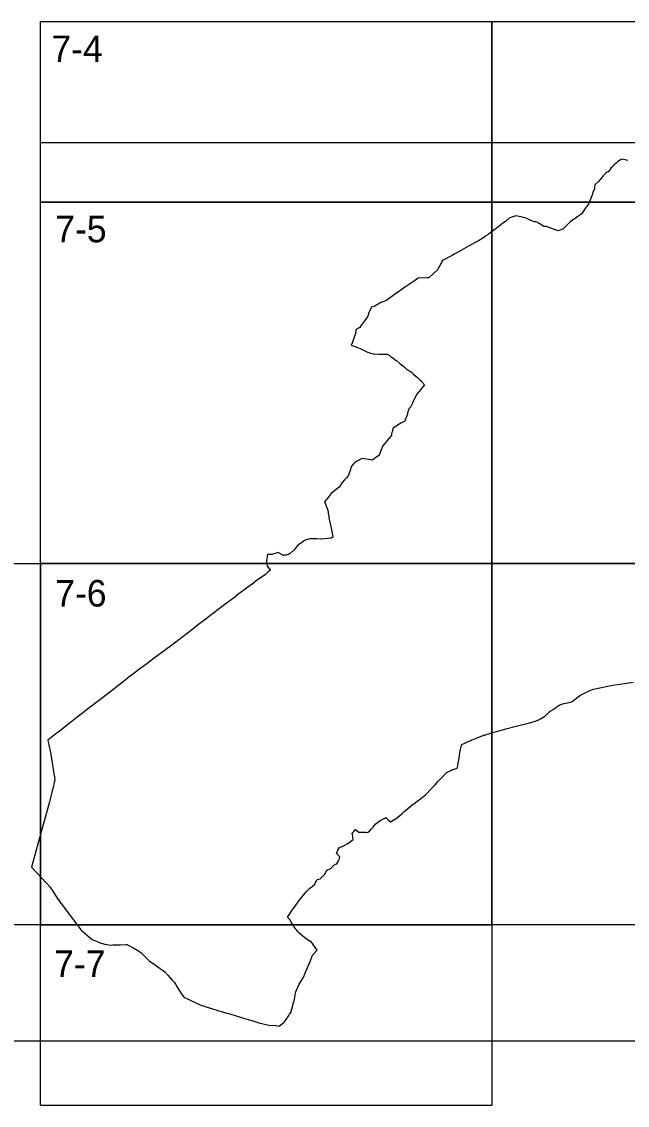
# Model space of a CAD drawing. Extents: x -449577 to -425530, y -1150048 to -1121091.
# Drawn here: x -438428.2 to -438218.5, y -1126653.4 to -1126278.4 of the extents above; entities that cross this region are included whole.
import ezdxf

# ---------------------------------------------------------------- set-up
doc = ezdxf.new("R2010")
doc.units = 0
for name, color, linetype in [('Vrstva 1', 7, 'Continuous'), ('Vrstva 10', 7, 'Continuous'), ('Vrstva 4', 7, 'Continuous')]:
    doc.layers.add(name, color=color, linetype=linetype)

msp = doc.modelspace()

# ---------------------------------------------------------------- linework, layer by layer
at = {"layer": 'Vrstva 1'}
for points in [[(-438218.3, -1126326.41), (-438218.76, -1126326.32), (-438220.35, -1126326), (-438220.65, -1126326.11), (-438221.21, -1126326.46), (-438221.76, -1126326.78), (-438222.25, -1126327.24), (-438222.78, -1126327.73), (-438223.18, -1126328.12), (-438223.19, -1126328.13), (-438223.52, -1126328.47), (-438223.65, -1126328.61), (-438224.16, -1126329.16), (-438224.61, -1126329.71), (-438224.77, -1126329.9), (-438225.13, -1126330.33), (-438225.87, -1126330.66), (-438225.89, -1126330.66), (-438226.09, -1126330.91), (-438226.95, -1126331.93), (-438227.33, -1126332.38), (-438228.46, -1126333.74), (-438228.47, -1126333.75), (-438229.71, -1126334.92), (-438229.83, -1126335.76), (-438229.88, -1126336.13), (-438229.92, -1126336.23), (-438230.4, -1126337.58), (-438230.84, -1126338.82), (-438230.87, -1126338.9), (-438231.17, -1126339.59), (-438232.1, -1126341.77), (-438232.12, -1126341.78), (-438232.69, -1126342.46), (-438232.99, -1126342.81), (-438232.99, -1126342.82), (-438233.33, -1126343.36), (-438234.2, -1126344.75), (-438234.29, -1126344.89), (-438234.46, -1126345.02), (-438234.99, -1126345.41), (-438235.6, -1126345.86), (-438235.6, -1126345.86), (-438236.57, -1126346.49), (-438236.7, -1126346.58), (-438236.88, -1126346.7), (-438238.18, -1126347.56), (-438238.19, -1126347.57), (-438238.45, -1126347.83), (-438238.57, -1126347.95), (-438238.79, -1126348.18), (-438239.07, -1126348.46), (-438239.64, -1126349.03), (-438240.8, -1126350.19), (-438241, -1126350.27), (-438242.5, -1126350.84), (-438245.31, -1126349.72), (-438245.31, -1126349.73), (-438245.32, -1126349.75), (-438246.23, -1126349.37), (-438246.54, -1126349.24), (-438246.56, -1126349.24), (-438246.95, -1126349.24), (-438247.43, -1126349.24), (-438248.99, -1126348.25), (-438249.25, -1126348.12), (-438249.54, -1126347.96), (-438249.6, -1126347.93), (-438249.64, -1126347.91), (-438250.18, -1126347.68), (-438250.23, -1126347.68), (-438250.24, -1126347.68), (-438250.39, -1126347.67), (-438250.51, -1126347.66), (-438250.82, -1126347.64), (-438250.84, -1126347.64), (-438250.84, -1126347.64), (-438250.95, -1126347.6), (-438251.19, -1126347.5), (-438251.79, -1126347.25), (-438251.95, -1126347.18), (-438253.47, -1126346.45), (-438254.09, -1126346.27), (-438254.76, -1126346.07), (-438257.08, -1126345.64), (-438257.09, -1126345.64), (-438257.49, -1126345.75), (-438259.23, -1126346.33), (-438259.36, -1126346.44), (-438260.57, -1126347.4), (-438260.57, -1126347.4), (-438261.72, -1126348.27), (-438262.29, -1126348.7), (-438262.87, -1126349.14), (-438263.03, -1126349.26), (-438265.16, -1126350.9), (-438266.23, -1126351.72), (-438266.7, -1126352.06), (-438267.46, -1126352.57), (-438267.71, -1126352.73), (-438268.3, -1126353.12), (-438268.34, -1126353.15), (-438268.55, -1126353.29), (-438269.46, -1126353.89), (-438269.47, -1126353.89), (-438269.94, -1126354.15), (-438270.09, -1126354.23), (-438270.27, -1126354.33), (-438270.73, -1126354.58), (-438270.91, -1126354.69), (-438271.07, -1126354.78), (-438271.17, -1126354.84), (-438271.41, -1126354.98), (-438273.07, -1126355.92), (-438273.24, -1126356.01), (-438273.47, -1126356.14), (-438275.94, -1126357.54), (-438276.06, -1126357.61), (-438278.17, -1126358.74), (-438279.19, -1126359.29), (-438282.53, -1126361.1), (-438282.7, -1126361.4), (-438282.76, -1126361.51), (-438283.54, -1126362.97), (-438284.22, -1126364.29), (-438284.36, -1126364.42), (-438284.45, -1126364.5), (-438285.59, -1126365.54), (-438287.1, -1126366.92), (-438287.27, -1126367.07), (-438287.27, -1126367.08), (-438287.74, -1126367.09), (-438290.93, -1126367.18), (-438290.94, -1126367.18), (-438291.37, -1126367.47), (-438292.2, -1126368.04), (-438294.67, -1126369.7), (-438294.71, -1126369.72), (-438294.95, -1126369.9), (-438295.22, -1126370.1), (-438298.2, -1126372.23), (-438298.27, -1126372.28), (-438301.27, -1126374.46), (-438301.74, -1126374.8), (-438301.9, -1126374.86), (-438303.84, -1126375.58), (-438303.85, -1126375.58), (-438304.24, -1126375.82), (-438306.12, -1126376.98), (-438307.04, -1126377.19), (-438307.29, -1126377.7), (-438308.05, -1126379.21), (-438308.06, -1126379.22), (-438308.13, -1126379.48), (-438308.33, -1126380.32), (-438309.16, -1126381.43), (-438310.53, -1126383.38), (-438311.09, -1126384.19), (-438311.12, -1126384.21), (-438312.28, -1126384.85), (-438312.38, -1126384.91), (-438312.45, -1126385.3), (-438312.6, -1126386.11), (-438312.65, -1126386.3), (-438313.94, -1126389.88), (-438314.11, -1126390.36), (-438314.08, -1126390.35), (-438314.06, -1126390.34), (-438313.38, -1126390.6), (-438311.57, -1126391.26), (-438310.95, -1126391.55), (-438308.66, -1126392.63), (-438308.64, -1126392.63), (-438307.48, -1126393.1), (-438307.01, -1126393.28), (-438306.98, -1126393.29), (-438306.55, -1126393.32), (-438306.41, -1126393.33), (-438306.19, -1126393.35), (-438304.59, -1126393.45), (-438303.55, -1126393.52), (-438302.5, -1126393.49), (-438301.66, -1126393.46), (-438301.65, -1126393.46), (-438301.37, -1126393.61), (-438301, -1126393.87), (-438300.45, -1126394.25), (-438300.06, -1126394.53), (-438298.5, -1126395.67), (-438298.33, -1126395.79), (-438297.22, -1126396.71), (-438296.83, -1126397.03), (-438296.65, -1126397.18), (-438295.9, -1126397.79), (-438295.63, -1126398.02), (-438295.03, -1126398.51), (-438294.81, -1126398.69), (-438294.17, -1126399.11), (-438293.42, -1126399.61), (-438293.39, -1126399.63), (-438292.63, -1126400.31), (-438291.75, -1126401.09), (-438291.31, -1126401.47), (-438290.3, -1126402.36), (-438290.04, -1126402.59), (-438289.99, -1126402.64), (-438289.89, -1126402.74), (-438289.88, -1126402.75), (-438289.79, -1126402.85), (-438289.76, -1126402.88), (-438288.71, -1126404.11), (-438288.72, -1126404.12), (-438289.16, -1126404.61), (-438289.22, -1126404.68), (-438289.79, -1126405.31), (-438290.61, -1126406.37), (-438290.78, -1126406.58), (-438291.34, -1126407.3), (-438291.64, -1126407.83), (-438291.66, -1126407.87), (-438291.67, -1126407.89), (-438291.8, -1126408.17), (-438292.6, -1126409.84), (-438292.91, -1126410.48), (-438293.53, -1126411.77), (-438293.64, -1126412.01), (-438293.65, -1126412.01), (-438293.69, -1126412.04), (-438293.98, -1126412.24), (-438294.06, -1126412.28), (-438294.11, -1126412.38), (-438294.2, -1126412.58), (-438294.29, -1126412.86), (-438294.46, -1126413.42), (-438294.47, -1126413.44), (-438294.59, -1126413.94), (-438294.61, -1126414.01), (-438294.6, -1126414.07), (-438294.59, -1126414.15), (-438294.59, -1126414.22), (-438294.6, -1126414.27), (-438295.48, -1126416.6), (-438295.5, -1126416.65), (-438295.52, -1126416.69), (-438295.53, -1126416.7), (-438296.23, -1126417), (-438296.48, -1126417.11), (-438296.95, -1126417.35), (-438299.56, -1126419.04), (-438299.56, -1126419.04), (-438299.93, -1126420.35), (-438300.01, -1126420.61), (-438300.12, -1126421.03), (-438300.18, -1126421.24), (-438300.18, -1126421.25), (-438300.17, -1126421.25), (-438300, -1126421.41), (-438300.01, -1126421.42), (-438300.37, -1126421.81), (-438301.17, -1126422.81), (-438301.18, -1126422.82), (-438301.39, -1126423.07), (-438301.39, -1126423.08), (-438301.51, -1126423.23), (-438302.67, -1126424.58), (-438303.21, -1126425.21), (-438303.97, -1126427.16), (-438304.35, -1126428.18), (-438304.48, -1126428.53), (-438306.01, -1126429.63), (-438306.63, -1126430.07), (-438306.81, -1126430.11), (-438306.83, -1126430.11), (-438307.46, -1126430.02), (-438310.3, -1126429.6), (-438310.79, -1126429.84), (-438312.12, -1126430.48), (-438312.66, -1126430.74), (-438312.69, -1126430.77), (-438313.12, -1126431.18), (-438313.29, -1126431.4), (-438313.95, -1126432.25), (-438313.95, -1126432.26), (-438314.62, -1126434.06), (-438315.19, -1126435.56), (-438315.19, -1126435.56), (-438315.33, -1126435.78), (-438315.66, -1126436.15), (-438316.38, -1126436.95), (-438317.08, -1126437.72), (-438317.09, -1126437.74), (-438317.22, -1126437.93), (-438318.29, -1126439.5), (-438318.76, -1126439.88), (-438320.33, -1126441.14), (-438321, -1126441.68), (-438321.1, -1126441.76), (-438321.13, -1126441.8), (-438322.25, -1126443.23), (-438323.39, -1126444.54), (-438323.24, -1126444.71), (-438323.23, -1126444.74), (-438323.23, -1126444.75), (-438322.22, -1126447.51), (-438321.94, -1126449.17), (-438321.62, -1126451.12), (-438321.21, -1126453.08), (-438320.48, -1126456.58), (-438320.44, -1126456.78), (-438321.09, -1126457.12), (-438321.21, -1126457.19), (-438324.38, -1126457.45), (-438324.54, -1126457.45), (-438326.03, -1126457.42), (-438328.42, -1126457.4), (-438329.7, -1126457.67), (-438330.3, -1126457.94), (-438331.28, -1126458.74), (-438332.58, -1126459.61), (-438332.67, -1126459.72), (-438333.83, -1126461.14), (-438335.28, -1126462.48), (-438335.97, -1126462.8), (-438336.57, -1126463.08), (-438337.74, -1126463.01), (-438339.35, -1126462.16), (-438341.59, -1126462.83), (-438343.07, -1126462.8), (-438343.45, -1126464.91), (-438343.46, -1126464.93), (-438343.47, -1126465.02), (-438343.18, -1126466.83), (-438342.21, -1126468.15), (-438342.2, -1126468.17), (-438342.94, -1126468.92), (-438343.55, -1126469.48), (-438343.8, -1126469.71), (-438344.6, -1126470.34), (-438346.53, -1126471.57), (-438346.59, -1126471.61), (-438348.56, -1126473.14), (-438348.62, -1126473.18), (-438349.11, -1126473.56), (-438353.77, -1126477.02), (-438353.8, -1126477.05), (-438358.75, -1126480.81), (-438363.01, -1126484.06), (-438363.89, -1126484.72), (-438366.46, -1126486.66), (-438370.46, -1126489.79), (-438372.9, -1126491.66), (-438376.21, -1126494.19), (-438376.26, -1126494.23), (-438381.05, -1126497.74), (-438381.28, -1126497.92), (-438384.89, -1126500.6), (-438387.28, -1126502.42), (-438389.25, -1126503.9), (-438391.57, -1126505.65), (-438391.8, -1126505.82), (-438392.93, -1126506.71), (-438397.75, -1126510.51), (-438401.64, -1126513.46), (-438405.86, -1126516.71), (-438407.15, -1126517.71), (-438409.54, -1126519.59), (-438410.72, -1126520.51), (-438414.66, -1126523.56), (-438415.59, -1126524.27), (-438416.83, -1126525.23), (-438419.15, -1126527.03), (-438419.15, -1126527.03), (-438419.11, -1126527.21), (-438418.82, -1126528.59), (-438418.79, -1126528.75), (-438418.26, -1126531.29), (-438418.1, -1126532.02), (-438418.1, -1126532.06), (-438417.17, -1126537.94), (-438417.16, -1126537.97), (-438416.86, -1126539.7), (-438416.86, -1126539.72), (-438416.8, -1126540.09), (-438416.74, -1126540.51), (-438416.77, -1126540.88), (-438416.92, -1126541.61), (-438417.3, -1126543.4), (-438417.59, -1126544.58), (-438417.61, -1126544.63), (-438418.72, -1126548.8), (-438420.82, -1126556.68), (-438422.81, -1126563.9), (-438424.74, -1126571), (-438424.75, -1126571.04), (-438419.47, -1126576.64), (-438418.42, -1126577.77), (-438417.66, -1126578.99), (-438415.64, -1126582.05), (-438415.59, -1126582.12), (-438414.58, -1126583.53), (-438414.42, -1126583.74), (-438412.54, -1126586.22), (-438411.97, -1126586.96), (-438411.94, -1126587), (-438411.42, -1126587.72), (-438410.04, -1126589.62), (-438409.71, -1126590.07), (-438407.56, -1126592.79), (-438406.16, -1126594.01), (-438403.76, -1126595.99), (-438402.02, -1126596.74), (-438400.83, -1126597.26), (-438400.7, -1126597.31), (-438399.37, -1126597.59), (-438399.23, -1126597.62), (-438397.61, -1126597.95), (-438397.58, -1126597.95), (-438396.62, -1126597.93), (-438396.24, -1126597.93), (-438395.72, -1126597.92), (-438395.04, -1126597.91), (-438394.13, -1126597.87), (-438392.18, -1126597.71), (-438391.73, -1126597.78), (-438391.07, -1126598.13), (-438389.35, -1126599.08), (-438387.39, -1126600.18), (-438386.87, -1126600.66), (-438386.15, -1126601.34), (-438385.35, -1126602.09), (-438384.03, -1126603.39), (-438383.89, -1126603.49), (-438382.7, -1126604.34), (-438380.29, -1126606.05), (-438378.65, -1126607.23), (-438377.6, -1126608.41), (-438375.96, -1126610.23), (-438375.32, -1126610.94), (-438374.96, -1126611.53), (-438374.5, -1126612.27), (-438373.56, -1126613.74), (-438372.93, -1126614.66), (-438371.89, -1126616.1), (-438370.82, -1126616.61), (-438369.44, -1126617.26), (-438368.13, -1126617.87), (-438366.16, -1126618.76), (-438365.03, -1126619.11), (-438363.31, -1126619.68), (-438363.16, -1126619.73), (-438362.07, -1126620.05), (-438360.65, -1126620.47), (-438360.64, -1126620.47), (-438360.43, -1126620.53), (-438360.37, -1126620.55), (-438359.51, -1126620.81), (-438357.12, -1126621.5), (-438357, -1126621.54), (-438356.52, -1126621.68), (-438353.59, -1126622.55), (-438350.9, -1126623.38), (-438350.56, -1126623.48), (-438349.8, -1126623.71), (-438347.79, -1126624.33), (-438346.06, -1126624.88), (-438342.6, -1126625.62)], [(-438342.6, -1126625.62), (-438340.21, -1126625.81), (-438339.01, -1126626.04), (-438338.9, -1126625.95), (-438337.32, -1126624.68), (-438336.29, -1126623.2), (-438336.18, -1126623.05), (-438335.66, -1126622.29), (-438335.55, -1126622.12), (-438335.41, -1126621.89), (-438335.03, -1126621.26), (-438334.76, -1126620.43), (-438334.74, -1126620.36), (-438334.72, -1126620.31), (-438334.69, -1126620.2), (-438334.66, -1126620.11), (-438334.66, -1126620.1), (-438334.03, -1126617.9), (-438333.89, -1126617.38), (-438333.44, -1126614.63), (-438333.44, -1126614.63), (-438333.25, -1126614.19), (-438332.99, -1126613.57), (-438332.2, -1126611.74), (-438330.63, -1126609.09), (-438328.88, -1126604.96), (-438328.56, -1126604.32), (-438328.52, -1126604.19), (-438328.13, -1126603.09), (-438327.54, -1126601.42), (-438325.86, -1126599.71), (-438326.79, -1126598.47), (-438326.85, -1126598.38), (-438326.9, -1126598.32), (-438326.93, -1126598.28), (-438327, -1126598.18), (-438327.05, -1126598.1), (-438327.13, -1126597.98), (-438327.49, -1126597.46), (-438327.86, -1126597), (-438328.43, -1126596.63), (-438328.53, -1126596.57), (-438330.18, -1126595.5), (-438332.37, -1126593.56), (-438332.5, -1126593.39), (-438332.53, -1126593.35), (-438332.61, -1126593.25), (-438332.95, -1126592.83), (-438333.28, -1126592.42), (-438333.54, -1126592.1), (-438334.02, -1126591.51), (-438334.1, -1126591.41), (-438334.6, -1126590.45), (-438334.89, -1126589.89), (-438335.12, -1126589.46), (-438335.17, -1126589.37), (-438335.21, -1126589.32), (-438335.47, -1126589.03), (-438335.67, -1126588.8), (-438335.93, -1126588.51), (-438336.15, -1126588.26), (-438334.29, -1126585.52), (-438334.2, -1126585.4), (-438333.88, -1126584.95), (-438333.56, -1126584.51), (-438332.23, -1126582.68), (-438329.55, -1126579.42), (-438329.2, -1126579.1), (-438328.49, -1126578.4), (-438328.38, -1126578.31), (-438328.19, -1126578.17), (-438327.59, -1126577.69), (-438326.73, -1126576.85), (-438326.32, -1126576.09), (-438325.85, -1126575.22), (-438324.8, -1126574.98), (-438323.4, -1126573.55), (-438322.86, -1126572.7), (-438322.85, -1126572.69), (-438322.85, -1126572.67), (-438322.64, -1126572.34), (-438322.59, -1126572.26), (-438322.35, -1126571.87), (-438321.19, -1126571.43), (-438320.17, -1126570.25), (-438319.64, -1126570.05), (-438319.52, -1126570), (-438319.1, -1126569.84), (-438318.88, -1126569.45), (-438318.83, -1126569.36), (-438318.66, -1126569.06), (-438318.25, -1126568.32), (-438318.05, -1126567.41), (-438318.05, -1126567.39), (-438318.04, -1126567.38), (-438319.09, -1126566.39), (-438319.11, -1126566.38), (-438319.12, -1126566.36), (-438319.17, -1126566.32), (-438318.52, -1126564.52), (-438318.45, -1126564.32), (-438318.29, -1126564.26), (-438317.56, -1126563.97), (-438316.87, -1126563.7), (-438316.75, -1126563.65), (-438315.54, -1126562.94), (-438315.42, -1126562.86), (-438315.42, -1126562.86), (-438315.41, -1126562.85), (-438315.29, -1126562.78), (-438313.43, -1126561.38), (-438313.43, -1126561.34), (-438313.46, -1126561.18), (-438313.53, -1126560.7), (-438313.59, -1126560.35), (-438313.69, -1126559.73), (-438313.71, -1126559.62), (-438313.73, -1126559.49), (-438313.75, -1126559.32), (-438313.78, -1126559.18), (-438313.24, -1126558.62), (-438312.68, -1126558.05), (-438312.64, -1126558), (-438312.5, -1126558.1), (-438311.5, -1126558.89), (-438310.82, -1126558.9), (-438310.76, -1126558.9), (-438310.51, -1126558.91), (-438310.35, -1126558.91), (-438309.04, -1126558.93), (-438308.41, -1126558.95), (-438308.14, -1126558.79), (-438308.11, -1126558.77), (-438307.99, -1126558.7), (-438307.85, -1126558.61), (-438307.81, -1126558.58), (-438307.27, -1126557.98), (-438307.16, -1126557.86), (-438307.07, -1126557.76), (-438306.9, -1126557.58), (-438306.82, -1126557.49), (-438306.71, -1126557.37), (-438306.68, -1126557.33), (-438306.65, -1126557.3), (-438306.6, -1126557.24), (-438306.51, -1126557.13), (-438306.11, -1126556.63), (-438305.9, -1126556.37), (-438305.65, -1126556.05), (-438305.54, -1126555.97), (-438304.08, -1126554.9), (-438303.87, -1126554.77), (-438302.51, -1126554), (-438302.11, -1126553.77), (-438302.11, -1126553.77), (-438301.97, -1126553.92), (-438301.26, -1126554.63), (-438300.89, -1126555.01), (-438300.71, -1126555.18), (-438300.56, -1126555.33), (-438300.47, -1126555.29), (-438299.19, -1126554.52), (-438299.1, -1126554.47), (-438298.17, -1126553.91), (-438298.13, -1126553.88), (-438297.8, -1126553.59), (-438297.75, -1126553.55), (-438297.58, -1126553.4), (-438297.57, -1126553.39), (-438297.57, -1126553.39), (-438297.53, -1126553.35), (-438297.49, -1126553.31), (-438296.6, -1126552.5), (-438296.58, -1126552.49), (-438295.99, -1126551.95), (-438295.88, -1126551.86), (-438295.77, -1126551.76), (-438295.77, -1126551.76), (-438295.76, -1126551.76), (-438295.76, -1126551.76), (-438295.76, -1126551.75), (-438295.75, -1126551.75), (-438295.74, -1126551.74), (-438295.74, -1126551.74), (-438295.73, -1126551.73), (-438295.73, -1126551.73), (-438295.72, -1126551.73), (-438295.72, -1126551.73), (-438295.14, -1126551.24), (-438293.15, -1126549.56), (-438291.95, -1126548.71), (-438291.83, -1126548.63), (-438291.78, -1126548.59), (-438291.76, -1126548.58), (-438291.71, -1126548.55), (-438291.35, -1126548.28), (-438290.11, -1126547.34), (-438289.93, -1126547.2), (-438289.72, -1126547.04), (-438289.7, -1126547.02), (-438288.82, -1126546.35), (-438288.47, -1126546.08), (-438288.42, -1126546.02), (-438288.33, -1126545.92), (-438287.69, -1126545.24), (-438286.79, -1126544.26), (-438285.43, -1126542.85), (-438285.21, -1126542.62), (-438284.96, -1126542.34), (-438284.12, -1126541.39), (-438283.83, -1126541.07), (-438283.63, -1126540.86), (-438283.34, -1126540.54), (-438282.16, -1126539.35), (-438281.23, -1126538.33), (-438279.17, -1126537.32), (-438279.01, -1126537.27), (-438278.81, -1126537.19), (-438277.37, -1126536.7), (-438277.22, -1126535.83), (-438277.06, -1126534.96), (-438276.64, -1126532.59), (-438276.56, -1126532.12), (-438276.23, -1126530.24), (-438276.03, -1126529.36), (-438276, -1126529.24), (-438275.95, -1126529.05), (-438275.94, -1126529.01), (-438275.92, -1126528.94), (-438275.91, -1126528.9), (-438275.9, -1126528.85), (-438275.89, -1126528.81), (-438275.88, -1126528.79), (-438275.82, -1126528.58), (-438274.74, -1126528.04), (-438274.45, -1126527.9), (-438274.43, -1126527.89), (-438274.18, -1126527.76), (-438274.13, -1126527.74), (-438272.36, -1126527.02), (-438272.33, -1126527.01), (-438272.3, -1126526.99), (-438271.5, -1126526.68), (-438270.54, -1126526.28), (-438269.73, -1126525.94), (-438268.79, -1126525.55), (-438268.71, -1126525.52), (-438268.1, -1126525.28), (-438268.25, -1126525.44), (-438268.01, -1126525.35), (-438267.52, -1126525.15), (-438266.99, -1126524.99), (-438265.29, -1126524.47), (-438264.7, -1126524.3), (-438264.25, -1126524.18), (-438263.36, -1126523.93), (-438262.05, -1126523.55), (-438260.51, -1126523.09), (-438256.97, -1126522.22), (-438254.2, -1126521.55), (-438253.53, -1126521.34), (-438252.04, -1126520.98), (-438251.83, -1126520.92), (-438250.4, -1126520.53), (-438249.8, -1126520.27), (-438249.58, -1126520.17), (-438249.42, -1126520.11), (-438248.6, -1126519.66), (-438248.54, -1126519.62), (-438247.23, -1126518.84), (-438246.08, -1126517.79), (-438245.43, -1126517.29), (-438245.3, -1126517.18), (-438245.28, -1126517.17), (-438245.12, -1126517.04), (-438244.97, -1126516.94), (-438244.17, -1126516.38), (-438244.11, -1126516.34), (-438244.04, -1126516.29), (-438243.53, -1126515.94), (-438243.16, -1126515.68), (-438242.5, -1126515.22), (-438241.91, -1126514.81), (-438241.75, -1126514.84), (-438241.74, -1126514.84), (-438241.72, -1126514.82), (-438240.99, -1126514.43), (-438238.03, -1126513.85), (-438237.61, -1126513.7), (-438235.58, -1126512.07), (-438235.11, -1126511.73), (-438235.08, -1126511.71), (-438234.72, -1126511.45), (-438234.54, -1126511.33), (-438233.15, -1126510.63), (-438231.74, -1126509.99), (-438231.44, -1126509.84), (-438230.18, -1126509.38), (-438229.18, -1126509.13), (-438223.47, -1126508.07), (-438222.05, -1126507.81), (-438220.34, -1126507.56), (-438216.47, -1126506.99)]]:
    msp.add_lwpolyline(points, dxfattribs=at)
at = {"layer": 'Vrstva 10'}
msp.add_lwpolyline([(-438109.21, -1126320.23), (-438109.21, -1126631.21), (-438442.08, -1126631.21), (-438442.08, -1126465.91), (-438421.71, -1126465.91), (-438421.71, -1126340.91), (-438421.71, -1126320.23), (-438109.21, -1126320.23)], dxfattribs=at)
at = {"layer": 'Vrstva 4'}
for p, q in [((-438421.71, -1126278.41), (-438109.21, -1126278.41)), ((-438421.71, -1126653.41), (-438265.46, -1126653.41))]:
    msp.add_line(p, q, dxfattribs=at)
for points in [[(-438265.46, -1126278.41), (-438265.46, -1126340.91), (-438421.71, -1126340.91), (-438421.71, -1126278.41)], [(-438109.21, -1126278.41), (-438109.21, -1126340.91), (-438265.46, -1126340.91), (-438265.46, -1126278.41)], [(-438499.84, -1126465.91), (-438421.71, -1126465.91), (-438421.71, -1126590.91), (-438499.84, -1126590.91)], [(-438421.71, -1126653.41), (-438421.71, -1126590.91), (-438265.46, -1126590.91), (-438265.46, -1126653.41)]]:
    msp.add_lwpolyline(points, dxfattribs=at)
for points in [[(-438265.46, -1126340.91), (-438265.46, -1126465.91), (-438421.71, -1126465.91), (-438421.71, -1126340.91)], [(-438109.21, -1126340.91), (-438109.21, -1126465.91), (-438265.46, -1126465.91), (-438265.46, -1126340.91)], [(-438265.46, -1126465.91), (-438265.46, -1126590.91), (-438421.71, -1126590.91), (-438421.71, -1126465.91)], [(-438109.21, -1126465.91), (-438109.21, -1126590.91), (-438265.46, -1126590.91), (-438265.46, -1126465.91)]]:
    msp.add_lwpolyline(points, close=True, dxfattribs=at)

# ---------------------------------------------------------------- texts
at = {"layer": 'Vrstva 1'}
for s, p in [('7-4', (-438417.9, -1126292.41)), ('7-5', (-438416.59, -1126354.75)), ('7-6', (-438416.59, -1126480.82)), ('7-7', (-438416.95, -1126608.99))]:
    msp.add_text(s, height=9.2, dxfattribs=at).set_placement(p)

doc.saveas('drawing.dxf')
